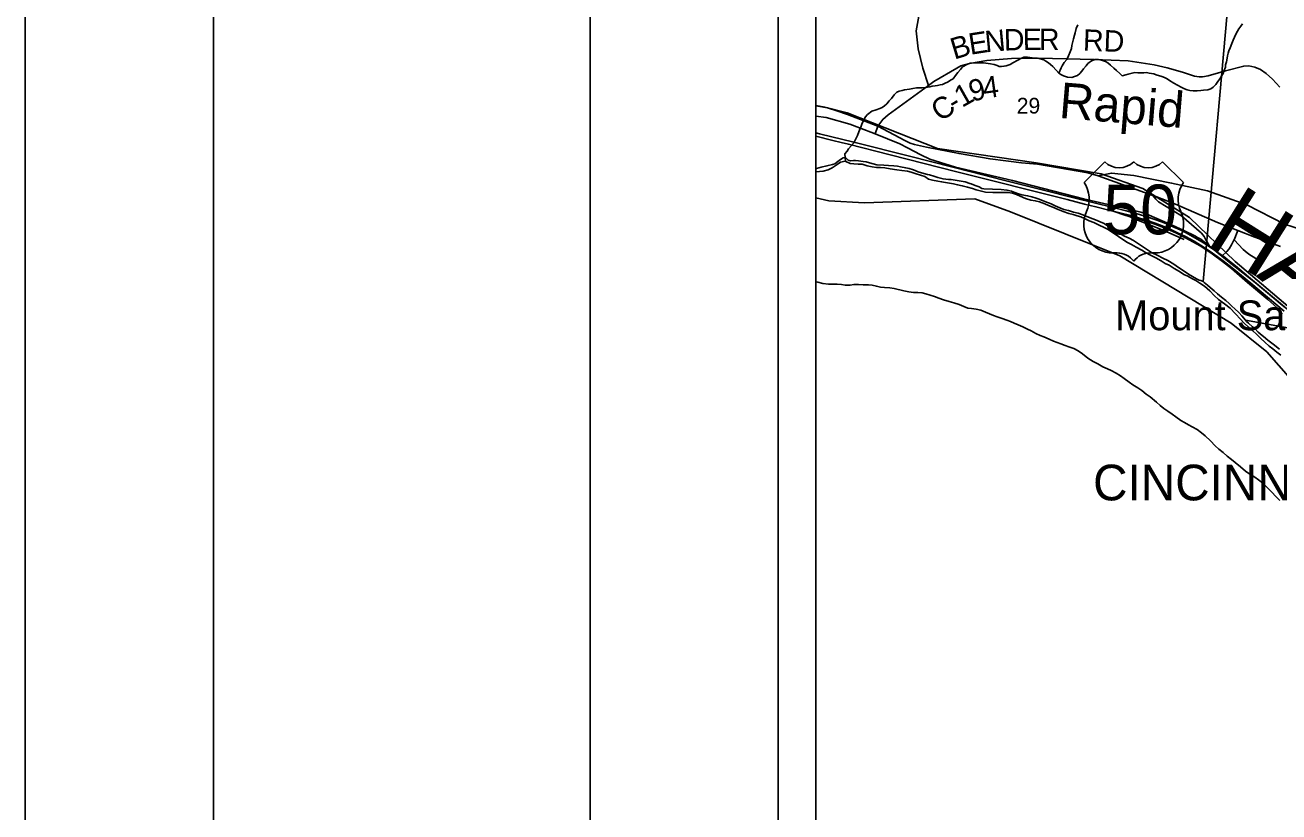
# Model space of a CAD drawing. Extents: x 0 to 34, y -2 to 22.
# Drawn here: x 0 to 3.329, y 14.734 to 16.823 of the extents above; entities that cross this region are included whole.
import ezdxf

# ---------------------------------------------------------------- set-up
doc = ezdxf.new("R2010")
doc.units = 0
for name, color, linetype in [('Default', 7, 'Continuous'), ('GM_X_City_Street', 7, 'Continuous'), ('GM_X_Corporation_Text', 7, 'Continuous'), ('GM_X_County_Road', 7, 'Continuous'), ('GM_X_County_Road_Text', 7, 'Continuous'), ('GM_X_County_Text', 7, 'Continuous'), ('GM_X_Major_River', 7, 'Continuous'), ('GM_X_Minor_River', 7, 'Continuous'), ('GM_X_Minor_River_Text', 7, 'Continuous'), ('GM_X_Rail_Line', 7, 'Continuous'), ('GM_X_Section', 7, 'Continuous'), ('GM_X_Section_Text', 7, 'Continuous'), ('GM_X_Unincorporated_Text', 7, 'Continuous'), ('GM_X_US_Location', 7, 'Continuous'), ('GM_X_US_Route', 7, 'Continuous'), ('GM_X_US_Shield', 7, 'Continuous'), ('SH_Border', 7, 'Continuous'), ('SH_Cut_Line', 7, 'Continuous'), ('SH_Data', 7, 'Continuous')]:
    doc.layers.add(name, color=color, linetype=linetype)

msp = doc.modelspace()

# ---------------------------------------------------------------- linework, layer by layer
at = {"layer": 'Default'}
msp.add_lwpolyline([(2.1, 16.9374), (2.1, 16.4427), (2.1014, 16.4429), (2.1136, 16.4464), (2.1288, 16.4494), (2.1441, 16.4528), (2.1498, 16.4554), (2.1583, 16.4612), (2.1652, 16.4667), (2.1725, 16.4711), (2.1786, 16.4717), (2.1816, 16.4686), (2.1856, 16.4643), (2.192, 16.463), (2.2, 16.464), (2.2053, 16.4642), (2.2133, 16.4629), (2.2253, 16.4611), (2.2329, 16.4602), (2.2423, 16.458), (2.2517, 16.4552), (2.2619, 16.4523), (2.28, 16.4518), (2.2925, 16.4508), (2.3069, 16.45), (2.3163, 16.4487), (2.3246, 16.4469), (2.3382, 16.444), (2.3476, 16.4426), (2.3585, 16.4393), (2.3713, 16.4341), (2.386, 16.4295), (2.3961, 16.427), (2.4014, 16.4254), (2.4127, 16.4225), (2.4236, 16.4184), (2.4375, 16.415), (2.4515, 16.4136), (2.459, 16.413), (2.4798, 16.4098), (2.496, 16.4068), (2.5088, 16.4027), (2.5118, 16.4019), (2.5227, 16.3978), (2.5336, 16.3938), (2.5403, 16.3898), (2.546, 16.3885), (2.5918, 16.3867), (2.6069, 16.3852), (2.6193, 16.3822), (2.6257, 16.3802), (2.6377, 16.3757), (2.6464, 16.3728), (2.6618, 16.3702), (2.6735, 16.3673), (2.6844, 16.364), (2.693, 16.3611), (2.7077, 16.3554), (2.7242, 16.3486), (2.7347, 16.3434), (2.7471, 16.3386), (2.7583, 16.3341), (2.7703, 16.3308), (2.7839, 16.3271), (2.7959, 16.3241), (2.8087, 16.3196), (2.8279, 16.312), (2.8421, 16.3063), (2.8549, 16.3011), (2.865, 16.2963), (2.8739, 16.2908), (2.8974, 16.2751), (2.9191, 16.2632), (2.9315, 16.2576), (2.9431, 16.2516), (2.9587, 16.241), (2.9804, 16.2268), (2.9908, 16.2198), (3.008, 16.2114), (3.0207, 16.2046), (3.0342, 16.1982), (3.0499, 16.1884), (3.0629, 16.1801), (3.0749, 16.1719), (3.0916, 16.1605), (3.095, 16.1585), (3.1043, 16.1534), (3.1122, 16.149), (3.1178, 16.1466), (3.122, 16.1454), (3.1283, 16.1422), (3.2017, 16.9647)], dxfattribs=at)
at = {"layer": 'GM_X_City_Street'}
for points in [[(3.1451, 16.2364), (3.1346, 16.255), (3.1306, 16.2621), (3.1238, 16.2707), (3.0706, 16.3173), (3.0091, 16.3544), (3.0024, 16.3611), (2.9944, 16.3713)], [(3.1774, 16.2102), (3.1909, 16.2222), (3.1967, 16.2295), (3.2032, 16.2404), (3.2089, 16.2507), (3.21, 16.2536), (3.22, 16.278)], [(3.21, 16.2536), (3.2346, 16.2275), (3.2445, 16.2185), (3.2521, 16.2135), (3.2765, 16.1983)]]:
    msp.add_lwpolyline(points, dxfattribs=at)
at = {"layer": 'GM_X_County_Road'}
msp.add_line((2.2569, 16.5344), (2.2644, 16.5553), dxfattribs=at)
for points in [[(2.3983, 16.6632), (2.3834, 16.7094), (2.3711, 16.7603), (2.3659, 16.8077), (2.3728, 16.8466)], [(2.3983, 16.6632), (2.4126, 16.6738), (2.4741, 16.7089), (2.4844, 16.7151), (2.5073, 16.7218), (2.5538, 16.7291), (2.6191, 16.7349), (2.6904, 16.7356), (2.8383, 16.7324), (2.9285, 16.7286), (2.9632, 16.7233), (2.9976, 16.7176), (3.032, 16.71), (3.0731, 16.6981), (3.1051, 16.6879), (3.1175, 16.6861), (3.1263, 16.6863), (3.1415, 16.689), (3.1877, 16.7021), (3.2357, 16.7147), (3.249, 16.7151), (3.2649, 16.7114), (3.2799, 16.7054), (3.2952, 16.6952), (3.3124, 16.68), (3.3312, 16.6587)], [(2.2644, 16.5553), (2.2773, 16.5728), (2.2916, 16.5847), (2.3983, 16.6632)], [(2.1, 16.6092), (2.1308, 16.6033), (2.1557, 16.5953), (2.1835, 16.5862), (2.2644, 16.5553)], [(2.2644, 16.5553), (2.3356, 16.5173), (2.3502, 16.5098), (2.3619, 16.5065), (2.3936, 16.4994), (2.4801, 16.4823), (2.5621, 16.468), (2.6457, 16.4575), (2.6881, 16.4543), (2.8214, 16.4313), (2.8489, 16.4235), (2.9944, 16.3713), (2.9976, 16.3702), (3.0544, 16.3481), (3.1659, 16.299), (3.1998, 16.2857), (3.22, 16.278), (3.2656, 16.2604), (3.3333, 16.2351)], [(2.8489, 16.4235), (2.8842, 16.4304), (2.9442, 16.4237), (3.044, 16.4037), (3.1395, 16.3837), (3.2438, 16.346), (3.3437, 16.2949), (3.4547, 16.2594), (3.5324, 16.2394), (3.6323, 16.2238), (3.6942, 16.2188)]]:
    msp.add_lwpolyline(points, dxfattribs=at)
at = {"layer": 'GM_X_Major_River'}
for points in [[(2.2611, 16.4455), (2.2494, 16.4469), (2.2358, 16.4501), (2.2222, 16.4537), (2.2119, 16.4543), (2.2009, 16.4548), (2.1911, 16.4561), (2.1779, 16.4624), (2.1654, 16.4596), (2.1558, 16.4533), (2.1427, 16.4444), (2.1324, 16.4392), (2.1195, 16.4356), (2.1096, 16.4343), (2.1, 16.4337)], [(3.334, 15.9471), (3.3239, 15.9549), (3.3134, 15.9638), (3.3036, 15.9708), (3.2917, 15.982), (3.2808, 15.9913), (3.2708, 16.0017), (3.2592, 16.0121), (3.2483, 16.0218), (3.236, 16.0333), (3.2274, 16.043), (3.214, 16.0565), (3.1994, 16.0715), (3.1848, 16.0831), (3.1687, 16.0944), (3.1571, 16.1056), (3.1459, 16.1179), (3.132, 16.1303), (3.1189, 16.1385), (3.1084, 16.1451), (3.0982, 16.1502), (3.0873, 16.1564), (3.0771, 16.1615), (3.0651, 16.1689), (3.0512, 16.1767), (3.0377, 16.1857), (3.0275, 16.1908), (3.0166, 16.1974), (3.0027, 16.2052), (2.9884, 16.2127), (2.9753, 16.2193), (2.9651, 16.2259), (2.9505, 16.2341), (2.9377, 16.2412), (2.9267, 16.2459), (2.9151, 16.2541), (2.9031, 16.2622), (2.8761, 16.2809), (2.8648, 16.286), (2.8516, 16.2923), (2.8373, 16.2993), (2.8249, 16.3041), (2.8132, 16.31), (2.8034, 16.3139), (2.7936, 16.3171), (2.783, 16.3203), (2.7717, 16.3235), (2.7562, 16.3283), (2.7426, 16.3339), (2.7287, 16.3402), (2.7178, 16.3441), (2.7072, 16.3489), (2.6936, 16.3544), (2.6823, 16.3572), (2.6706, 16.3589), (2.6566, 16.3629), (2.6419, 16.3696), (2.6321, 16.3732), (2.6215, 16.3768), (2.6106, 16.3785), (2.6007, 16.379), (2.5901, 16.3788), (2.5802, 16.379), (2.5696, 16.3788), (2.5499, 16.3802), (2.5363, 16.3831), (2.5253, 16.3863), (2.5155, 16.3895), (2.5027, 16.3931), (2.4883, 16.3967), (2.4759, 16.3996), (2.4649, 16.4021), (2.4494, 16.4046), (2.4335, 16.4075), (2.4237, 16.4092), (2.4097, 16.412), (2.3991, 16.4145), (2.3893, 16.4211), (2.3772, 16.4247), (2.3659, 16.4287), (2.3531, 16.4331), (2.3433, 16.4355), (2.3278, 16.4376), (2.3149, 16.439), (2.2971, 16.4419), (2.2827, 16.4444), (2.271, 16.445), (2.2611, 16.4455)], [(2.1, 16.1418), (2.1053, 16.1405), (2.1186, 16.1369), (2.133, 16.1352), (2.1451, 16.1357), (2.1561, 16.1359), (2.1678, 16.1346), (2.1777, 16.1333), (2.191, 16.1331), (2.2008, 16.1348), (2.213, 16.135), (2.2255, 16.1341), (2.2391, 16.1335), (2.249, 16.1326), (2.2603, 16.1301), (2.2713, 16.128), (2.2815, 16.1267), (2.2963, 16.1254), (2.3076, 16.1237), (2.3333, 16.1179), (2.3466, 16.1154), (2.3591, 16.1133), (2.3701, 16.1132), (2.3818, 16.1122), (2.392, 16.1098), (2.4033, 16.1062), (2.4147, 16.1026), (2.426, 16.0982), (2.4388, 16.0939), (2.4539, 16.0891), (2.4656, 16.0858), (2.4803, 16.0818), (2.4928, 16.0763), (2.5029, 16.0716), (2.5132, 16.0707), (2.5253, 16.0693), (2.5374, 16.0661), (2.5502, 16.061), (2.5604, 16.057), (2.5713, 16.0523), (2.5811, 16.0487), (2.5939, 16.0447), (2.6064, 16.0403), (2.6162, 16.036), (2.6264, 16.032), (2.6365, 16.0277), (2.6493, 16.0222), (2.6618, 16.0163), (2.6716, 16.0116), (2.6836, 16.0046), (2.6953, 15.9991), (2.7051, 15.9955), (2.719, 15.9892), (2.7307, 15.9845), (2.7405, 15.9809), (2.7503, 15.9769), (2.7616, 15.9726), (2.7714, 15.9694), (2.7846, 15.9646), (2.7963, 15.9587), (2.8079, 15.951), (2.8214, 15.939), (2.8357, 15.93), (2.8481, 15.9241), (2.8616, 15.9163), (2.8741, 15.9108), (2.8838, 15.9061), (2.8974, 15.8994), (2.9083, 15.8924), (2.9184, 15.8847), (2.9315, 15.875), (2.9413, 15.868), (2.9548, 15.8602), (2.9653, 15.8532), (2.9769, 15.8439), (2.9871, 15.8361)], [(2.9871, 15.8361), (3.0039, 15.8222), (3.0136, 15.8137), (3.0238, 15.8056), (3.0339, 15.7982), (3.0455, 15.79), (3.0556, 15.783), (3.0684, 15.7737), (3.0782, 15.7683), (3.0887, 15.762), (3.0989, 15.7569), (3.112, 15.7495), (3.1237, 15.7413), (3.1334, 15.7325), (3.1472, 15.7197), (3.1603, 15.7066), (3.17, 15.6973), (3.1812, 15.6884), (3.1921, 15.6791), (3.2033, 15.6702), (3.2131, 15.6621), (3.2273, 15.6505), (3.2408, 15.6389), (3.252, 15.6315), (3.2656, 15.6233), (3.2753, 15.6163), (3.2866, 15.6074), (3.3008, 15.5935), (3.3112, 15.5827), (3.3205, 15.5727), (3.3317, 15.5615)]]:
    msp.add_lwpolyline(points, dxfattribs=at)
at = {"layer": 'GM_X_Minor_River'}
for points in [[(2.7447, 16.6958), (2.7511, 16.7098), (2.7539, 16.7154), (2.7594, 16.7237), (2.7664, 16.7319), (2.7704, 16.7421), (2.7748, 16.7523), (2.778, 16.761), (2.7793, 16.7689), (2.781, 16.7761), (2.7834, 16.7867), (2.7863, 16.7966), (2.7879, 16.8026), (2.7908, 16.8147), (2.7952, 16.8242)], [(2.9226, 16.6911), (2.9291, 16.6929), (2.9391, 16.6958), (2.9468, 16.6971), (2.9548, 16.697), (2.9701, 16.6967), (2.9773, 16.6977), (2.9846, 16.6961), (2.9967, 16.6936), (3.0036, 16.6912), (3.018, 16.6871), (3.0252, 16.684), (3.032, 16.6804), (3.0388, 16.6761), (3.0501, 16.6691), (3.06, 16.6636), (3.0698, 16.6584), (3.0785, 16.6545), (3.0853, 16.6517), (3.0926, 16.6497), (3.1017, 16.6488), (3.112, 16.6486), (3.1216, 16.6499), (3.1292, 16.6505), (3.1407, 16.6519), (3.148, 16.6544), (3.1542, 16.6588), (3.1616, 16.6659), (3.1671, 16.6734), (3.1725, 16.6806), (3.1765, 16.6877), (3.1812, 16.6952), (3.1832, 16.7009), (3.1869, 16.7115), (3.1877, 16.7179), (3.1902, 16.7262), (3.1919, 16.7357), (3.1928, 16.7418), (3.1944, 16.749), (3.1961, 16.755), (3.1996, 16.7626), (3.2044, 16.7746), (3.2073, 16.7833), (3.2116, 16.7916), (3.216, 16.8007), (3.2192, 16.8074), (3.2231, 16.8135), (3.2278, 16.8202), (3.2325, 16.8266)], [(2.1788, 16.462), (2.1768, 16.4817), (2.1827, 16.4888), (2.1862, 16.4948), (2.1933, 16.5031), (2.2003, 16.5109), (2.2042, 16.5177), (2.2074, 16.5245), (2.2098, 16.5301), (2.2162, 16.5467), (2.2198, 16.555), (2.223, 16.5626), (2.2277, 16.5716), (2.2309, 16.5792), (2.2372, 16.5863), (2.2484, 16.5944), (2.2595, 16.5984), (2.2691, 16.6017), (2.2757, 16.6046), (2.2822, 16.609), (2.2881, 16.6146), (2.2947, 16.6221), (2.3005, 16.6285), (2.3076, 16.6386), (2.3146, 16.645), (2.3208, 16.6479), (2.3288, 16.65), (2.335, 16.6514), (2.348, 16.6535), (2.3572, 16.6552), (2.3671, 16.6569), (2.3748, 16.6572), (2.3816, 16.6571), (2.3908, 16.658), (2.4023, 16.6594), (2.4081, 16.6612), (2.4161, 16.6622), (2.423, 16.6632), (2.4295, 16.6646), (2.4356, 16.6656), (2.4414, 16.6682), (2.4507, 16.6726), (2.4572, 16.6774), (2.4638, 16.6811), (2.4704, 16.6893), (2.4763, 16.6972), (2.4833, 16.705), (2.4888, 16.7122), (2.5004, 16.7188), (2.5092, 16.7224), (2.5196, 16.7234), (2.5261, 16.7233), (2.5337, 16.7235), (2.5444, 16.7233), (2.563, 16.7207), (2.5729, 16.7183), (2.5809, 16.7158), (2.5866, 16.7138), (2.5923, 16.7137), (2.5988, 16.714), (2.6046, 16.715), (2.6157, 16.719), (2.623, 16.7227), (2.6358, 16.7301), (2.6435, 16.7349), (2.6523, 16.7381), (2.6615, 16.738), (2.6741, 16.7362), (2.6817, 16.7357), (2.6882, 16.7352), (2.695, 16.7339), (2.7049, 16.7307), (2.7106, 16.7276), (2.7174, 16.7229), (2.723, 16.719), (2.7286, 16.7132), (2.7376, 16.7035), (2.7447, 16.6958), (2.7504, 16.6919), (2.7572, 16.6887), (2.7675, 16.6851), (2.7789, 16.6842), (2.7866, 16.6867), (2.7943, 16.6896), (2.8009, 16.6952), (2.8056, 16.7008), (2.8099, 16.7068), (2.8177, 16.7154), (2.8216, 16.721), (2.8313, 16.7281), (2.8416, 16.7321), (2.8493, 16.732), (2.8584, 16.7299), (2.8686, 16.7263), (2.8751, 16.7235), (2.8822, 16.7173), (2.8912, 16.7092), (2.898, 16.703), (2.907, 16.6944), (2.913, 16.689), (2.9226, 16.6911)]]:
    msp.add_lwpolyline(points, dxfattribs=at)
at = {"layer": 'GM_X_Rail_Line'}
msp.add_line((3.3329, 16.0607), (3.3253, 16.0715), dxfattribs=at)
for points in [[(3.6832, 17.9108), (3.2869, 17.9604), (2.9298, 18.0171), (2.3446, 18.1102), (2.1, 18.1368), (2.1, 16.3648), (2.1342, 16.3571), (2.2291, 16.3515), (2.5217, 16.3621), (2.6166, 16.3275), (2.9069, 16.2111), (3.202, 16.0321), (3.297, 15.9555), (3.6339, 15.5717)], [(2.1, 16.6096), (2.1239, 16.6051), (2.1832, 16.5905), (2.4225, 16.4957), (2.6844, 16.4575), (2.8574, 16.4285), (2.9674, 16.3896), (3.0918, 16.3125), (3.2132, 16.1958), (3.4289, 16.0129)], [(2.1, 16.5372), (2.1091, 16.5349), (2.2004, 16.5125), (2.3518, 16.4742), (2.5117, 16.4337), (2.5946, 16.4125), (2.7009, 16.3861), (2.7886, 16.3642), (2.889, 16.339), (2.9237, 16.3303), (2.9524, 16.3226), (2.9797, 16.3144), (2.9972, 16.3085), (3.017, 16.3012), (3.0375, 16.2927), (3.0505, 16.2871), (3.0671, 16.2794), (3.0831, 16.2714), (3.0996, 16.2625), (3.1142, 16.2543), (3.1292, 16.2453), (3.1494, 16.2321), (3.1673, 16.2199), (3.1825, 16.2086), (3.1983, 16.1964), (3.2138, 16.1838), (3.2483, 16.155), (3.3436, 16.0755)], [(2.1, 16.5283), (2.1448, 16.517), (2.1665, 16.5119), (2.1862, 16.5069), (2.2967, 16.479), (2.4738, 16.4341), (2.7671, 16.3599), (2.8133, 16.3483), (2.8431, 16.3409), (2.8779, 16.332), (2.9065, 16.325), (2.9395, 16.3166), (2.9587, 16.3109), (2.9803, 16.3043), (3.0007, 16.2971), (3.0189, 16.2904), (3.0407, 16.2813), (3.0581, 16.2731), (3.0809, 16.2618), (3.1037, 16.2498), (3.1212, 16.2394), (3.1363, 16.2297), (3.1532, 16.2182), (3.1811, 16.1978), (3.2048, 16.1791), (3.2545, 16.138), (3.3428, 16.0636)], [(2.8867, 16.3299), (2.9228, 16.3179), (2.9387, 16.3138), (2.9579, 16.3081), (2.9794, 16.3015), (2.9997, 16.2944), (3.0179, 16.2877), (3.0396, 16.2787), (3.0568, 16.2706), (3.0795, 16.2593), (3.1023, 16.2473), (3.1197, 16.237), (3.1347, 16.2273), (3.1515, 16.2159), (3.1793, 16.1955), (3.2029, 16.1769), (3.246, 16.1399)], [(2.9296, 16.3162), (2.9565, 16.3049), (3.0233, 16.278), (3.0773, 16.2537)], [(3.3253, 16.0715), (3.3155, 16.0806), (3.2993, 16.0951), (3.246, 16.1399), (3.2228, 16.1642)], [(3.3376, 16.0571), (3.3257, 16.0712), (3.3253, 16.0715)]]:
    msp.add_lwpolyline(points, dxfattribs=at)
at = {"layer": 'GM_X_Section'}
msp.add_lwpolyline([(4.1192, 16.9159), (4.012, 15.9002), (3.2406, 16.0402), (3.231, 16.0514), (3.2225, 16.0599), (3.2118, 16.0701), (3.2044, 16.0774), (3.197, 16.0844), (3.1881, 16.0918), (3.1769, 16.1008), (3.1658, 16.1098), (3.1569, 16.1176), (3.1469, 16.1266), (3.1398, 16.1328), (3.1309, 16.1402), (3.1283, 16.1422), (3.2017, 16.9647)], close=True, dxfattribs=at)
msp.add_lwpolyline([(3.3308, 15.9634), (3.3141, 15.9759), (3.2999, 15.9865), (3.2884, 15.997), (3.2851, 15.9997), (3.2739, 16.0079), (3.2643, 16.0184), (3.2591, 16.0227), (3.248, 16.0321), (3.2432, 16.0367), (3.2406, 16.0402), (4.012, 15.9002)], dxfattribs=at)
at = {"layer": 'GM_X_US_Route'}
for points in [[(2.1, 16.5818), (2.1266, 16.5783), (2.1895, 16.5606), (2.2153, 16.5506), (2.2569, 16.5344), (2.3223, 16.5079), (2.3426, 16.4975), (2.3786, 16.4788), (2.4027, 16.4675), (2.4707, 16.4465), (2.6218, 16.4108), (2.8102, 16.3621), (2.9182, 16.3374), (2.9628, 16.3267), (2.9781, 16.3218), (3.0454, 16.2922), (3.0784, 16.277), (3.1055, 16.264), (3.1134, 16.2597), (3.1221, 16.2549), (3.1451, 16.2364), (3.1532, 16.2299)], [(3.1532, 16.2299), (3.1774, 16.2102), (3.1927, 16.1978), (3.2662, 16.1399), (3.3381, 16.0797), (3.4113, 16.0236), (3.454, 15.9871), (3.4937, 15.9512), (3.5323, 15.9084), (3.5719, 15.8607), (3.6379, 15.7814), (3.8444, 15.531), (3.9609, 15.3865), (4.0346, 15.2981), (4.0555, 15.2744), (4.0718, 15.2578), (4.1217, 15.218)]]:
    msp.add_lwpolyline(points, dxfattribs=at)
at = {"layer": 'GM_X_US_Shield'}
for p, q in [((2.8666, 16.4602), (2.8117, 16.4053)), ((3.0754, 16.4053), (3.0204, 16.4602)), ((2.8886, 16.2185), (2.8996, 16.2185)), ((2.9875, 16.2185), (2.9985, 16.2185))]:
    msp.add_line(p, q, dxfattribs=at)
for centre, radius, start, end in [((2.9051, 16.4995), 0.0549, 225.573, 314.427), ((2.982, 16.4995), 0.0549, 225.573, 314.427), ((2.7487, 16.3612), 0.0769, 334.5471, 35.0009), ((3.1384, 16.3612), 0.0769, 144.9991, 205.4529), ((2.8878, 16.2954), 0.0769, 154.8319, 270.6383), ((2.9993, 16.2954), 0.0769, 269.3617, 25.1681), ((2.8996, 16.1636), 0.0549, 36.8699, 90), ((2.9875, 16.1636), 0.0549, 90, 143.1301)]:
    msp.add_arc(centre, radius, start, end, dxfattribs=at)
at = {"layer": 'SH_Border'}
for points in [[(0.5, 21.5), (1.5, 21.5), (1.5, 0.5), (0.5, 0.5)], [(1.5, 21.5), (33.5, 21.5), (33.5, 0.5), (1.5, 0.5)]]:
    msp.add_lwpolyline(points, close=True, dxfattribs=at)
at = {"layer": 'SH_Cut_Line'}
msp.add_lwpolyline([(0, 0), (34, 0), (34, 22), (0, 22)], close=True, dxfattribs=at)
msp.add_lwpolyline([(8.9, 20.9), (2.1, 20.9), (2.1, 16.3648), (2.1342, 16.3571), (2.2291, 16.3515), (2.5217, 16.3621), (2.6166, 16.3275), (2.9069, 16.2111), (3.202, 16.0321), (3.297, 15.9555), (3.6339, 15.5717)], dxfattribs=at)
at = {"layer": 'SH_Data'}
for p, q in [((2, 21), (2, 14)), ((2.1, 20.9), (2.1, 14.1))]:
    msp.add_line(p, q, dxfattribs=at)

# ---------------------------------------------------------------- texts
at = {"layer": 'GM_X_Corporation_Text'}
msp.add_text('CINCINNATI', height=0.0947, rotation=0, dxfattribs=at).set_placement((2.8357, 15.5616))
at = {"layer": 'GM_X_County_Road_Text'}
for s, height, rotation, p in [('D', 0.0568, 1.86, (2.5997, 16.7555)), ('E', 0.0568, 0.105, (2.6492, 16.7571)), ('R', 0.0568, 0.0078, (2.6917, 16.7571)), ('B', 0.0568, 16.7306, (2.4671, 16.7314)), ('E', 0.0568, 8.9244, (2.5098, 16.7443)), ('N', 0.0568, 5.3773, (2.5508, 16.7508)), ('RD', 0.05682, 358.026, (2.8082, 16.7555)), ('9', 0.0568, 15.5065, (2.5147, 16.619)), ('4', 0.0568, 7.8907, (2.5464, 16.628)), ('1', 0.0568, 29.4812, (2.4876, 16.6032)), ('C', 0.0568, 35.0785, (2.4307, 16.5651)), ('-', 0.0568, 31.1779, (2.468, 16.5914))]:
    msp.add_text(s, height=height, rotation=rotation, dxfattribs=at).set_placement(p)
at = {"layer": 'GM_X_County_Text'}
for s, rotation, p in [('H', 327.897, (3.1293, 16.2429)), ('A', 320.9905, (3.2662, 16.1574))]:
    msp.add_text(s, height=0.1894, rotation=rotation, dxfattribs=at).set_placement(p)
at = {"layer": 'GM_X_Minor_River_Text'}
msp.add_text('Rapid', height=0.0947, rotation=355.2876, dxfattribs=at).set_placement((2.7434, 16.5772))
at = {"layer": 'GM_X_Section_Text'}
msp.add_text('29', height=0.04186, rotation=0, dxfattribs=at).set_placement((2.6331, 16.5884))
at = {"layer": 'GM_X_Unincorporated_Text'}
msp.add_text('Mount Saint Joseph', height=0.078977, rotation=0, dxfattribs=at).set_placement((2.8944, 16.0133))
at = {"layer": 'GM_X_US_Location'}
for s in ['0', '/']:
    msp.add_text(s, height=0.000189, dxfattribs=at).set_placement((2.9435, 16.3328))
msp.add_text('50', height=0.000189, rotation=0, dxfattribs=at).set_placement((2.9044, 16.2936))
at = {"layer": 'GM_X_US_Shield'}
msp.add_text('50', height=0.13184, dxfattribs=at).set_placement((2.8626, 16.268))

doc.saveas('drawing.dxf')
